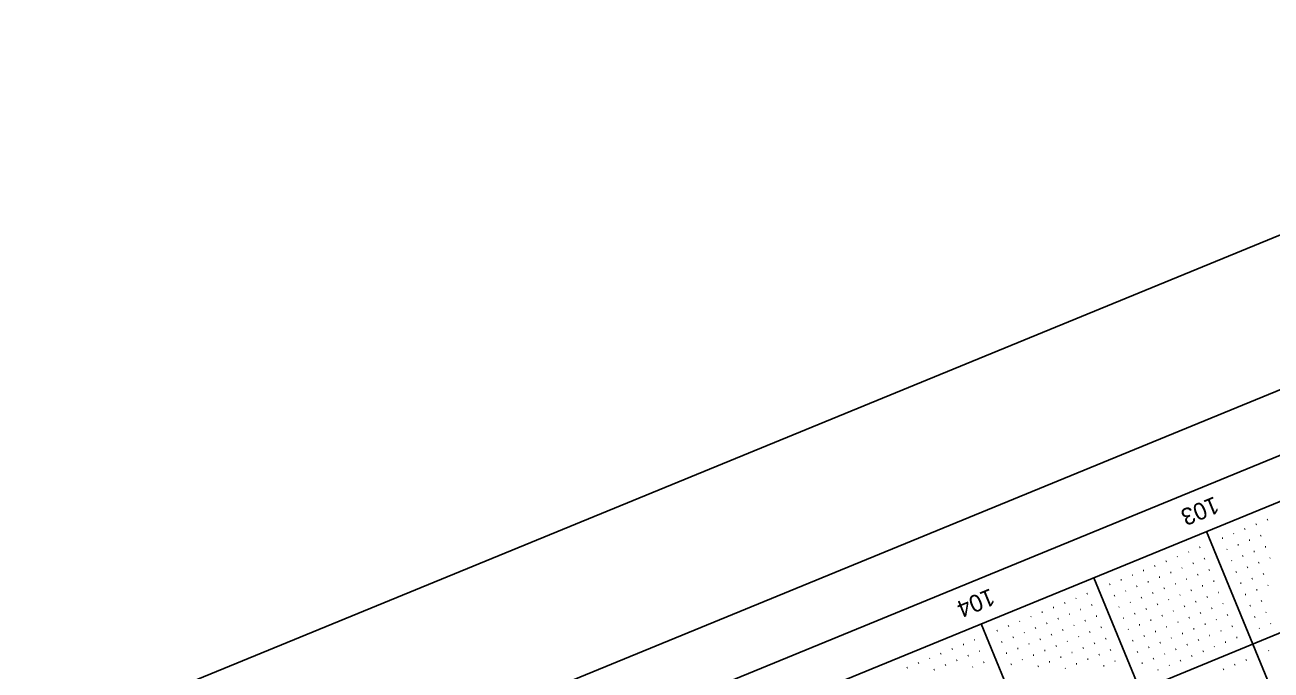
# Model space of a CAD drawing. Extents: x 2148770 to 2150891, y 142633 to 144465.
# Drawn here: x 2148770 to 2149282, y 143776 to 144041 of the extents above; entities that cross this region are included whole.
import ezdxf

# ---------------------------------------------------------------- set-up
doc = ezdxf.new("R2010")
doc.units = 0
for name, color, linetype in [('SHT_Plan_Profile_Sheet_Sta_Txt', 7, 'Continuous'), ('SHT_Plot_Shape_Full', 7, 'Continuous'), ('SHT_Plot_Shape_Half', 7, 'Continuous'), ('SHT_Profile_Grid_Major', 7, 'Continuous'), ('SHT_Profile_Grid_Minor', 7, 'Continuous'), ('SHT_Sheet_Border', 7, 'Continuous')]:
    doc.layers.add(name, color=color, linetype=linetype)

msp = doc.modelspace()

# ---------------------------------------------------------------- linework, layer by layer
at = {"layer": 'SHT_Plot_Shape_Full'}
msp.add_lwpolyline([(2150890.55, 143316.95), (2149225.42, 142633.31), (2148769.66, 143743.39), (2150434.78, 144427.04)], close=True, dxfattribs=at)
at = {"layer": 'SHT_Plot_Shape_Half'}
msp.add_lwpolyline([(2150799.14, 143324.02), (2149226.52, 142678.36), (2148808.74, 143695.93), (2150381.36, 144341.59)], close=True, dxfattribs=at)
at = {"layer": 'SHT_Profile_Grid_Major'}
for p, q in [((2150326.3, 144218.99), (2148869.31, 143620.81)), ((2149255.04, 143833.22), (2149435.48, 143393.74)), ((2149208.79, 143814.23), (2149389.22, 143374.75)), ((2149162.53, 143795.24), (2149342.97, 143355.76))]:
    msp.add_line(p, q, dxfattribs=at)
at = {"layer": 'SHT_Profile_Grid_Minor'}
for p, q in [((2149270.93, 143834.34), (2149270.7, 143834.25)), ((2149275.56, 143836.24), (2149275.32, 143836.15)), ((2149280.18, 143838.14), (2149279.95, 143838.04)), ((2149261.68, 143830.54), (2149261.45, 143830.45)), ((2149266.31, 143832.44), (2149266.07, 143832.35)), ((2149272.83, 143829.72), (2149272.6, 143829.62)), ((2149277.45, 143831.62), (2149277.22, 143831.52)), ((2149243.18, 143822.95), (2149242.95, 143822.85)), ((2149247.8, 143824.85), (2149247.57, 143824.75)), ((2149252.43, 143826.75), (2149252.2, 143826.65)), ((2149263.58, 143825.92), (2149263.35, 143825.82)), ((2149268.2, 143827.82), (2149267.97, 143827.72)), ((2149270.1, 143823.19), (2149269.87, 143823.1)), ((2149274.73, 143825.09), (2149274.5, 143825)), ((2149279.35, 143826.99), (2149279.12, 143826.89)), ((2149233.93, 143819.15), (2149233.7, 143819.05)), ((2149238.55, 143821.05), (2149238.32, 143820.95)), ((2149245.08, 143818.32), (2149244.85, 143818.23)), ((2149249.7, 143820.22), (2149249.47, 143820.13)), ((2149254.33, 143822.12), (2149254.1, 143822.03)), ((2149265.48, 143821.29), (2149265.25, 143821.2)), ((2149272, 143818.57), (2149271.77, 143818.47)), ((2149276.63, 143820.47), (2149276.4, 143820.37)), ((2149281.25, 143822.36), (2149281.02, 143822.27)), ((2149220.05, 143813.45), (2149219.82, 143813.36)), ((2149224.68, 143815.35), (2149224.45, 143815.26)), ((2149229.3, 143817.25), (2149229.07, 143817.16)), ((2149231.2, 143812.63), (2149230.97, 143812.53)), ((2149235.83, 143814.52), (2149235.6, 143814.43)), ((2149240.45, 143816.42), (2149240.22, 143816.33)), ((2149246.98, 143813.7), (2149246.75, 143813.6)), ((2149251.6, 143815.6), (2149251.37, 143815.5)), ((2149256.23, 143817.49), (2149256, 143817.4)), ((2149258.13, 143812.87), (2149257.89, 143812.77)), ((2149267.38, 143816.67), (2149267.15, 143816.57)), ((2149273.9, 143813.94), (2149273.67, 143813.85)), ((2149278.53, 143815.84), (2149278.3, 143815.75)), ((2149206.18, 143807.76), (2149205.94, 143807.66)), ((2149215.43, 143811.55), (2149215.2, 143811.46)), ((2149221.95, 143808.83), (2149221.72, 143808.73)), ((2149226.58, 143810.73), (2149226.34, 143810.63)), ((2149233.1, 143808), (2149232.87, 143807.9)), ((2149237.73, 143809.9), (2149237.49, 143809.8)), ((2149242.35, 143811.8), (2149242.12, 143811.7)), ((2149248.88, 143809.07), (2149248.64, 143808.98)), ((2149253.5, 143810.97), (2149253.27, 143810.88)), ((2149260.03, 143808.24), (2149259.79, 143808.15)), ((2149269.28, 143812.04), (2149269.04, 143811.95)), ((2149275.8, 143809.32), (2149275.57, 143809.22)), ((2149280.43, 143811.21), (2149280.19, 143811.12)), ((2149196.93, 143803.96), (2149196.69, 143803.86)), ((2149201.55, 143805.86), (2149201.32, 143805.76)), ((2149208.07, 143803.13), (2149207.84, 143803.04)), ((2149217.33, 143806.93), (2149217.09, 143806.83)), ((2149223.85, 143804.2), (2149223.62, 143804.11)), ((2149228.48, 143806.1), (2149228.24, 143806.01)), ((2149235, 143803.37), (2149234.77, 143803.28)), ((2149239.62, 143805.27), (2149239.39, 143805.18)), ((2149244.25, 143807.17), (2149244.02, 143807.08)), ((2149246.15, 143802.55), (2149245.92, 143802.45)), ((2149250.77, 143804.45), (2149250.54, 143804.35)), ((2149255.4, 143806.35), (2149255.17, 143806.25)), ((2149261.92, 143803.62), (2149261.69, 143803.52)), ((2149271.17, 143807.42), (2149270.94, 143807.32)), ((2149273.07, 143802.79), (2149272.84, 143802.7)), ((2149277.7, 143804.69), (2149277.47, 143804.6)), ((2149183.05, 143798.26), (2149182.82, 143798.17)), ((2149187.67, 143800.16), (2149187.44, 143800.06)), ((2149192.3, 143802.06), (2149192.07, 143801.96)), ((2149194.2, 143797.43), (2149193.97, 143797.34)), ((2149198.82, 143799.33), (2149198.59, 143799.24)), ((2149203.45, 143801.23), (2149203.22, 143801.14)), ((2149209.97, 143798.5), (2149209.74, 143798.41)), ((2149219.22, 143802.3), (2149218.99, 143802.21)), ((2149221.12, 143797.68), (2149220.89, 143797.58)), ((2149225.75, 143799.58), (2149225.52, 143799.48)), ((2149230.37, 143801.48), (2149230.14, 143801.38)), ((2149236.9, 143798.75), (2149236.67, 143798.65)), ((2149241.52, 143800.65), (2149241.29, 143800.55)), ((2149248.05, 143797.92), (2149247.82, 143797.83)), ((2149252.67, 143799.82), (2149252.44, 143799.73)), ((2149257.3, 143801.72), (2149257.07, 143801.62)), ((2149263.82, 143798.99), (2149263.59, 143798.9)), ((2149274.97, 143798.17), (2149274.74, 143798.07)), ((2149279.6, 143800.07), (2149279.37, 143799.97)), ((2149169.17, 143792.56), (2149168.94, 143792.47)), ((2149173.8, 143794.46), (2149173.57, 143794.37)), ((2149178.42, 143796.36), (2149178.19, 143796.27)), ((2149184.95, 143793.64), (2149184.72, 143793.54)), ((2149189.57, 143795.53), (2149189.34, 143795.44)), ((2149196.1, 143792.81), (2149195.87, 143792.71)), ((2149200.72, 143794.71), (2149200.49, 143794.61)), ((2149205.35, 143796.61), (2149205.12, 143796.51)), ((2149211.87, 143793.88), (2149211.64, 143793.78)), ((2149223.02, 143793.05), (2149222.79, 143792.96)), ((2149227.65, 143794.95), (2149227.42, 143794.86)), ((2149232.27, 143796.85), (2149232.04, 143796.76)), ((2149234.17, 143792.22), (2149233.94, 143792.13)), ((2149238.8, 143794.12), (2149238.57, 143794.03)), ((2149243.42, 143796.02), (2149243.19, 143795.93)), ((2149249.95, 143793.3), (2149249.72, 143793.2)), ((2149254.57, 143795.2), (2149254.34, 143795.1)), ((2149259.2, 143797.09), (2149258.97, 143797)), ((2149261.1, 143792.47), (2149260.87, 143792.37)), ((2149265.72, 143794.37), (2149265.49, 143794.27)), ((2149276.87, 143793.54), (2149276.64, 143793.45)), ((2149281.5, 143795.44), (2149281.27, 143795.34)), ((2149159.92, 143788.77), (2149159.69, 143788.67)), ((2149171.07, 143787.94), (2149170.84, 143787.84)), ((2149175.7, 143789.84), (2149175.47, 143789.74)), ((2149180.32, 143791.74), (2149180.09, 143791.64)), ((2149182.22, 143787.11), (2149181.99, 143787.02)), ((2149186.85, 143789.01), (2149186.62, 143788.91)), ((2149191.47, 143790.91), (2149191.24, 143790.81)), ((2149198, 143788.18), (2149197.77, 143788.09)), ((2149202.62, 143790.08), (2149202.39, 143789.99)), ((2149207.25, 143791.98), (2149207.02, 143791.89)), ((2149209.15, 143787.36), (2149208.92, 143787.26)), ((2149213.77, 143789.25), (2149213.54, 143789.16)), ((2149224.92, 143788.43), (2149224.69, 143788.33)), ((2149229.55, 143790.33), (2149229.32, 143790.23)), ((2149236.07, 143787.6), (2149235.84, 143787.5)), ((2149240.7, 143789.5), (2149240.47, 143789.4)), ((2149245.32, 143791.4), (2149245.09, 143791.3)), ((2149251.85, 143788.67), (2149251.61, 143788.58)), ((2149256.47, 143790.57), (2149256.24, 143790.48)), ((2149263, 143787.84), (2149262.76, 143787.75)), ((2149267.62, 143789.74), (2149267.39, 143789.65)), ((2149146.05, 143783.07), (2149145.82, 143782.97)), ((2149150.67, 143784.97), (2149150.44, 143784.87)), ((2149155.3, 143786.87), (2149155.07, 143786.77)), ((2149157.2, 143782.24), (2149156.96, 143782.15)), ((2149161.82, 143784.14), (2149161.59, 143784.05)), ((2149172.97, 143783.31), (2149172.74, 143783.22)), ((2149177.6, 143785.21), (2149177.37, 143785.12)), ((2149184.12, 143782.49), (2149183.89, 143782.39)), ((2149188.75, 143784.38), (2149188.51, 143784.29)), ((2149193.37, 143786.28), (2149193.14, 143786.19)), ((2149199.9, 143783.56), (2149199.66, 143783.46)), ((2149204.52, 143785.46), (2149204.29, 143785.36)), ((2149211.05, 143782.73), (2149210.81, 143782.63)), ((2149215.67, 143784.63), (2149215.44, 143784.53)), ((2149226.82, 143783.8), (2149226.59, 143783.71)), ((2149231.45, 143785.7), (2149231.21, 143785.61)), ((2149237.97, 143782.97), (2149237.74, 143782.88)), ((2149242.6, 143784.87), (2149242.36, 143784.78)), ((2149247.22, 143786.77), (2149246.99, 143786.68)), ((2149249.12, 143782.15), (2149248.89, 143782.05)), ((2149253.75, 143784.05), (2149253.51, 143783.95)), ((2149258.37, 143785.94), (2149258.14, 143785.85)), ((2149280.67, 143784.29), (2149280.44, 143784.2)), ((2149132.17, 143777.37), (2149131.94, 143777.28)), ((2149136.8, 143779.27), (2149136.56, 143779.18)), ((2149141.42, 143781.17), (2149141.19, 143781.07)), ((2149147.95, 143778.44), (2149147.71, 143778.35)), ((2149152.57, 143780.34), (2149152.34, 143780.25)), ((2149159.09, 143777.62), (2149158.86, 143777.52)), ((2149163.72, 143779.51), (2149163.49, 143779.42)), ((2149174.87, 143778.69), (2149174.64, 143778.59)), ((2149179.5, 143780.59), (2149179.26, 143780.49)), ((2149186.02, 143777.86), (2149185.79, 143777.77)), ((2149190.65, 143779.76), (2149190.41, 143779.66)), ((2149195.27, 143781.66), (2149195.04, 143781.56)), ((2149197.17, 143777.03), (2149196.94, 143776.94)), ((2149201.79, 143778.93), (2149201.56, 143778.84)), ((2149206.42, 143780.83), (2149206.19, 143780.74)), ((2149212.94, 143778.1), (2149212.71, 143778.01)), ((2149217.57, 143780), (2149217.34, 143779.91)), ((2149228.72, 143779.18), (2149228.49, 143779.08)), ((2149233.34, 143781.08), (2149233.11, 143780.98)), ((2149239.87, 143778.35), (2149239.64, 143778.25)), ((2149244.49, 143780.25), (2149244.26, 143780.15)), ((2149266.79, 143778.59), (2149266.56, 143778.5)), ((2149271.42, 143780.49), (2149271.19, 143780.4)), ((2149143.32, 143776.54), (2149143.09, 143776.45)), ((2149235.24, 143776.45), (2149235.01, 143776.35)), ((2149262.17, 143776.69), (2149261.94, 143776.6))]:
    msp.add_line(p, q, dxfattribs=at)
at = {"layer": 'SHT_Sheet_Border'}
msp.add_line((2150307.31, 144265.25), (2149093.15, 143766.76), dxfattribs=at)
msp.add_lwpolyline([(2150699.45, 143310.11), (2149242.47, 142711.93), (2148843.68, 143683.25), (2150300.66, 144281.43)], close=True, dxfattribs=at)

# ---------------------------------------------------------------- texts
at = {"layer": 'SHT_Plan_Profile_Sheet_Sta_Txt'}
for s, p in [('103', (2149258.3, 143847.8)), ('104', (2149166.24, 143810.01))]:
    msp.add_text(s, height=7, rotation=202.3213, dxfattribs=at).set_placement(p)

doc.saveas('drawing.dxf')
